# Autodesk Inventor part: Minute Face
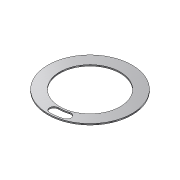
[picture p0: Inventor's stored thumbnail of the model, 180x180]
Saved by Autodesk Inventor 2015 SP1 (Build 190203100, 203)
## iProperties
Created: 2015-01
Part Number: Minute Face
Material: Generic
Document SubType Name: Modeling
Designer: Steve Brooks
Density: 1 g/cm^3
Appearance: Machined - Aluminum
Author: Steve Brooks
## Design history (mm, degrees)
sketch "Sketch1" dims "d21" = 55, "d24" = 390
  geometry: L1 (0, 0)-(51.76, -159.302); L2 (0, -187.5)-(0, -195); L3 (0, -147.5)-(0, -140); A1 r 20 centre (0, -167.5) between (0, -147.5) and (0, -187.5); A2 r 20 centre (51.76, -159.302) between (57.941, -178.323) and (45.58, -140.281); A3 r 167.5 centre (0, 0) between (0, -167.5) and (51.76, -159.302); A4 r 187.5 centre (0, 0) between (0, -187.5) and (57.941, -178.323); A5 r 147.5 centre (0, 0) between (0, -147.5) and (45.58, -140.281); 2 further points
  constraints: 12 point on circle, 6 end point, 5 centre point, 5 coincident, 3 tangent, 3 vertical alignment, 2 collinear, 1 point on line, 1 vertical, 4 other
  dimensions: "d0" = 40 diameter of A1; "d5" = 40 diameter of A2; "d25" = 18 deg angle of L1 L3
extrude "Extrusion2" new body sketch "Sketch1" distance "d7" = 6; taper "d8" = 0 deg
body "Solid2"
